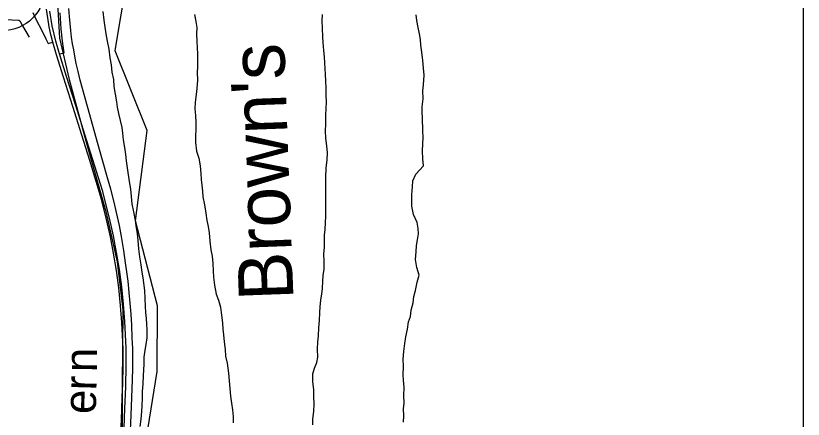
# Model space of a CAD drawing. Extents: x 2.1 to 8.9, y 14.1 to 20.9.
# Drawn here: x 7.533 to 8.9, y 15.741 to 16.441 of the extents above; entities that cross this region are included whole.
import ezdxf

# ---------------------------------------------------------------- set-up
doc = ezdxf.new("R2010")
doc.units = 0
for name, color, linetype in [('Default', 7, 'Continuous'), ('GM_X_City_Street', 7, 'Continuous'), ('GM_X_Major_River_Text', 7, 'Continuous'), ('GM_X_Rail_Line_Text', 7, 'Continuous'), ('GM_X_State_Location', 7, 'Continuous'), ('GM_X_State_Route', 7, 'Continuous'), ('GM_X_Unincorporated', 7, 'Continuous'), ('GM_X_Unincorporated_Location', 7, 'Continuous'), ('SC_Shading1', 7, 'Continuous'), ('SH_Cut_Line', 7, 'Continuous'), ('SH_Data', 7, 'Continuous')]:
    doc.layers.add(name, color=color, linetype=linetype)

msp = doc.modelspace()

# ---------------------------------------------------------------- linework, layer by layer
at = {"layer": 'Default'}
for p, q in [((7.7134, 16.4295), (7.7293, 16.5242)), ((7.7053, 16.3805), (7.7134, 16.4295)), ((7.7608, 16.2423), (7.7053, 16.3805)), ((7.7406, 16.0851), (7.7608, 16.2423)), ((7.7787, 15.9377), (7.7406, 16.0851)), ((7.7783, 15.8237), (7.7787, 15.9377)), ((7.7451, 15.6232), (7.7783, 15.8237))]:
    msp.add_line(p, q, dxfattribs=at)
at = {"layer": 'GM_X_City_Street'}
for p, q in [((7.4987, 16.4351), (7.5381, 16.4333)), ((7.5381, 16.4333), (7.5399, 16.4324)), ((7.5399, 16.4324), (7.5445, 16.4235)), ((7.5445, 16.4235), (7.5557, 16.4041))]:
    msp.add_line(p, q, dxfattribs=at)
at = {"layer": 'GM_X_Rail_Line_Text'}
for p, q in [((7.588, 16.4374), (7.5861, 16.4524)), ((7.5907, 16.4217), (7.588, 16.4374)), ((7.5958, 16.4236), (7.5916, 16.4493)), ((7.6019, 16.3969), (7.5958, 16.4236)), ((7.5937, 16.4084), (7.5907, 16.4217)), ((7.5968, 16.3954), (7.5937, 16.4084)), ((7.6084, 16.375), (7.6019, 16.3969)), ((7.6033, 16.3735), (7.5968, 16.3954)), ((7.6155, 16.3345), (7.6033, 16.3735)), ((7.6206, 16.336), (7.6084, 16.375)), ((7.6315, 16.2839), (7.6155, 16.3345)), ((7.6366, 16.2853), (7.6206, 16.336)), ((7.6473, 16.2339), (7.6315, 16.2839)), ((7.6524, 16.2354), (7.6366, 16.2853)), ((7.6612, 16.1898), (7.6473, 16.2339)), ((7.6663, 16.1913), (7.6524, 16.2354)), ((7.6795, 16.1487), (7.6663, 16.1913)), ((7.6723, 16.1538), (7.6612, 16.1898)), ((7.6807, 16.1249), (7.6723, 16.1538)), ((7.6835, 16.1363), (7.6795, 16.1487)), ((7.6901, 16.1104), (7.6835, 16.1363)), ((7.6854, 16.1068), (7.6807, 16.1249)), ((7.6954, 16.0899), (7.6901, 16.1104)), ((7.6903, 16.0879), (7.6854, 16.1068)), ((7.6971, 16.0576), (7.6903, 16.0879)), ((7.7022, 16.0591), (7.6954, 16.0899)), ((7.7024, 16.0291), (7.6971, 16.0576)), ((7.7074, 16.0306), (7.7022, 16.0591)), ((7.7072, 15.9989), (7.7024, 16.0291)), ((7.7124, 16.0008), (7.7074, 16.0306)), ((7.7165, 15.9707), (7.7124, 16.0008)), ((7.7114, 15.9688), (7.7072, 15.9989)), ((7.7146, 15.9386), (7.7114, 15.9688)), ((7.7197, 15.9407), (7.7165, 15.9707)), ((7.7168, 15.9087), (7.7146, 15.9386)), ((7.7222, 15.9106), (7.7197, 15.9407)), ((7.7181, 15.8861), (7.7168, 15.9087)), ((7.7233, 15.888), (7.7222, 15.9106)), ((7.7188, 15.8632), (7.7181, 15.8861)), ((7.7241, 15.8641), (7.7233, 15.888)), ((7.719, 15.833), (7.7188, 15.8632)), ((7.7244, 15.8351), (7.7241, 15.8641)), ((7.7184, 15.8024), (7.719, 15.833)), ((7.7235, 15.7971), (7.7244, 15.8351)), ((7.7176, 15.7797), (7.7184, 15.8024)), ((7.7222, 15.7595), (7.7235, 15.7971)), ((7.7167, 15.7573), (7.7176, 15.7797)), ((7.7157, 15.7267), (7.7167, 15.7573)), ((7.7202, 15.7063), (7.7222, 15.7595))]:
    msp.add_line(p, q, dxfattribs=at)
at = {"layer": 'GM_X_State_Location'}
for p, q in [((7.6836, 16.4485), (7.6854, 16.4334)), ((7.8432, 16.4432), (7.8453, 16.4315)), ((8.0647, 16.4322), (8.0649, 16.4432)), ((8.2292, 16.4331), (8.2279, 16.4429)), ((7.6854, 16.4334), (7.6875, 16.4212)), ((7.8453, 16.4315), (7.8467, 16.4209)), ((8.0653, 16.4197), (8.0647, 16.4322)), ((8.2313, 16.4206), (8.2292, 16.4331)), ((7.6875, 16.4212), (7.6892, 16.4099)), ((7.6892, 16.4099), (7.6914, 16.397)), ((7.8467, 16.4209), (7.8465, 16.4098)), ((7.8465, 16.4098), (7.8471, 16.3966)), ((8.066, 16.4049), (8.0653, 16.4197)), ((8.2334, 16.41), (8.2313, 16.4206)), ((8.2351, 16.4002), (8.2334, 16.41)), ((7.6914, 16.397), (7.6939, 16.383)), ((7.8471, 16.3966), (7.8477, 16.3859)), ((8.0662, 16.395), (8.066, 16.4049)), ((8.236, 16.3903), (8.2351, 16.4002)), ((7.6939, 16.383), (7.6961, 16.3682)), ((7.8477, 16.3859), (7.8483, 16.3746)), ((8.0676, 16.381), (8.0662, 16.395)), ((8.2378, 16.3778), (8.236, 16.3903)), ((7.8483, 16.3746), (7.8481, 16.3632)), ((8.0686, 16.37), (8.0676, 16.381)), ((8.0695, 16.3598), (8.0686, 16.37)), ((8.2396, 16.3638), (8.2378, 16.3778)), ((7.6961, 16.3682), (7.6982, 16.3561)), ((7.6982, 16.3561), (7.6996, 16.3432)), ((7.8481, 16.3632), (7.848, 16.3525)), ((8.0701, 16.3492), (8.0695, 16.3598)), ((8.2406, 16.3505), (8.2396, 16.3638)), ((7.6996, 16.3432), (7.7021, 16.3308)), ((7.848, 16.3525), (7.8474, 16.3426)), ((7.8474, 16.3426), (7.848, 16.3294)), ((8.0706, 16.3397), (8.0701, 16.3492)), ((8.2416, 16.3384), (8.2406, 16.3505)), ((7.7021, 16.3308), (7.7031, 16.3183)), ((7.848, 16.3294), (7.8471, 16.3149)), ((8.0712, 16.3279), (8.0706, 16.3397)), ((8.0718, 16.3162), (8.0712, 16.3279)), ((8.2404, 16.3213), (8.2416, 16.3384)), ((7.7031, 16.3183), (7.7052, 16.305)), ((7.8471, 16.3149), (7.8458, 16.3046)), ((8.0717, 16.3036), (8.0718, 16.3162)), ((8.2394, 16.311), (8.2404, 16.3213)), ((7.7052, 16.305), (7.7074, 16.2921)), ((7.8458, 16.3046), (7.8438, 16.2913)), ((8.0719, 16.2911), (8.0717, 16.3036)), ((8.2401, 16.2973), (8.2394, 16.311)), ((7.7074, 16.2921), (7.7087, 16.2823)), ((7.8438, 16.2913), (7.8436, 16.2799)), ((8.0717, 16.2808), (8.0719, 16.2911)), ((8.2384, 16.2833), (8.2401, 16.2973)), ((7.7087, 16.2823), (7.7112, 16.2717)), ((7.8436, 16.2799), (7.8446, 16.2682)), ((8.0712, 16.2679), (8.0717, 16.2808)), ((8.2382, 16.2738), (8.2384, 16.2833)), ((8.2388, 16.2643), (8.2382, 16.2738)), ((7.7112, 16.2717), (7.7137, 16.2596)), ((7.7137, 16.2596), (7.7165, 16.2475)), ((7.8446, 16.2682), (7.8452, 16.2557)), ((8.0708, 16.2531), (8.0712, 16.2679)), ((8.2392, 16.2415), (8.2388, 16.2643)), ((7.7165, 16.2475), (7.7179, 16.2373)), ((7.8452, 16.2557), (7.8455, 16.2435)), ((8.0706, 16.2417), (8.0708, 16.2531)), ((7.7179, 16.2373), (7.7192, 16.2259)), ((7.8449, 16.2329), (7.8447, 16.2215)), ((7.8455, 16.2435), (7.8449, 16.2329)), ((8.0712, 16.2288), (8.0706, 16.2417)), ((8.2398, 16.2298), (8.2392, 16.2415)), ((7.7192, 16.2259), (7.7214, 16.2127)), ((7.8447, 16.2215), (7.8466, 16.2063)), ((8.073, 16.2156), (8.0712, 16.2288)), ((8.2391, 16.2066), (8.2397, 16.2187)), ((8.2397, 16.2187), (8.2398, 16.2298)), ((7.7214, 16.2127), (7.7231, 16.2002)), ((7.8466, 16.2063), (7.8506, 16.1939)), ((8.0736, 16.2031), (8.073, 16.2156)), ((8.2394, 16.1929), (8.2391, 16.2066)), ((7.7231, 16.2002), (7.7245, 16.1896)), ((7.8506, 16.1939), (7.8527, 16.1806)), ((8.0735, 16.1909), (8.0736, 16.2031)), ((8.2404, 16.1808), (8.2394, 16.1929)), ((7.7245, 16.1896), (7.7262, 16.1775)), ((7.7262, 16.1775), (7.7293, 16.1536)), ((7.8527, 16.1806), (7.8537, 16.1674)), ((8.0718, 16.1768), (8.0735, 16.1909)), ((8.2274, 16.1661), (8.2404, 16.1808)), ((7.8537, 16.1674), (7.8547, 16.1571)), ((8.071, 16.1612), (8.0718, 16.1768)), ((8.2223, 16.1546), (8.2274, 16.1661)), ((7.7293, 16.1536), (7.7315, 16.14)), ((7.8547, 16.1571), (7.8556, 16.1473)), ((8.0707, 16.1381), (8.0712, 16.151)), ((8.0712, 16.151), (8.071, 16.1612)), ((8.2217, 16.1444), (8.2223, 16.1546)), ((7.7315, 16.14), (7.7328, 16.1275)), ((7.8556, 16.1473), (7.857, 16.1367)), ((7.857, 16.1367), (7.8575, 16.1268)), ((8.0712, 16.1282), (8.0707, 16.1381)), ((8.2205, 16.1307), (8.2217, 16.1444)), ((7.7328, 16.1275), (7.7342, 16.1146)), ((7.8575, 16.1268), (7.8601, 16.1132)), ((8.0708, 16.1126), (8.0712, 16.1282)), ((8.2203, 16.1212), (8.2205, 16.1307)), ((7.7342, 16.1146), (7.7368, 16.101)), ((7.8601, 16.1132), (7.8626, 16.0984)), ((8.071, 16.1028), (8.0708, 16.1126)), ((8.2205, 16.1109), (8.2203, 16.1212)), ((8.223, 16.0962), (8.2205, 16.1109)), ((7.7368, 16.101), (7.7397, 16.0862)), ((7.8626, 16.0984), (7.8644, 16.0859)), ((8.0708, 16.0929), (8.071, 16.1028)), ((8.2294, 16.0823), (8.223, 16.0962)), ((7.7397, 16.0862), (7.741, 16.0764)), ((7.8644, 16.0859), (7.8668, 16.0757)), ((8.0697, 16.0705), (8.0702, 16.0823)), ((8.0702, 16.0823), (8.0708, 16.0929)), ((8.2311, 16.072), (8.2294, 16.0823)), ((7.741, 16.0764), (7.7432, 16.0635)), ((7.8668, 16.0757), (7.8682, 16.0644)), ((8.0687, 16.0602), (8.0697, 16.0705)), ((8.2316, 16.0626), (8.2311, 16.072)), ((7.7432, 16.0635), (7.7445, 16.051)), ((7.8682, 16.0644), (7.8696, 16.05)), ((8.0686, 16.0496), (8.0687, 16.0602)), ((8.2299, 16.0523), (8.2316, 16.0626)), ((7.7445, 16.051), (7.7459, 16.037)), ((7.8696, 16.05), (7.8714, 16.0348)), ((8.0684, 16.0397), (8.0686, 16.0496)), ((8.2277, 16.0317), (8.2286, 16.0424)), ((8.2286, 16.0424), (8.2299, 16.0523)), ((7.7459, 16.037), (7.7477, 16.023)), ((7.8714, 16.0348), (7.8735, 16.0239)), ((8.0675, 16.0276), (8.0684, 16.0397)), ((8.0681, 16.0158), (8.0675, 16.0276)), ((8.2264, 16.0181), (8.2277, 16.0317)), ((7.7477, 16.023), (7.7499, 16.009)), ((7.8735, 16.0239), (7.8749, 16.0117)), ((8.068, 16.0014), (8.0681, 16.0158)), ((8.229, 16.0041), (8.2264, 16.0181)), ((7.7499, 16.009), (7.7516, 15.9961)), ((7.8749, 16.0117), (7.8751, 15.9977)), ((8.0663, 15.9903), (8.068, 16.0014)), ((8.233, 15.9912), (8.229, 16.0041)), ((7.7516, 15.9961), (7.7533, 15.9863)), ((7.7533, 15.9863), (7.756, 15.9643)), ((7.8751, 15.9977), (7.8757, 15.9878)), ((7.8757, 15.9878), (7.8775, 15.9738)), ((8.0657, 15.9805), (8.0663, 15.9903)), ((8.2298, 15.9787), (8.233, 15.9912)), ((7.8775, 15.9738), (7.8808, 15.9583)), ((8.0652, 15.9679), (8.0657, 15.9805)), ((8.2267, 15.9645), (8.2298, 15.9787)), ((7.756, 15.9643), (7.7567, 15.9507)), ((8.0642, 15.958), (8.0652, 15.9679)), ((8.2239, 15.9542), (8.2267, 15.9645)), ((7.7567, 15.9507), (7.7573, 15.9366)), ((7.8808, 15.9583), (7.8844, 15.9478)), ((7.8844, 15.9478), (7.8881, 15.9353)), ((8.0613, 15.936), (8.0625, 15.9485)), ((8.0625, 15.9485), (8.0642, 15.958)), ((8.2229, 15.9428), (8.2239, 15.9542)), ((7.7573, 15.9366), (7.7579, 15.9264)), ((7.8881, 15.9353), (7.8899, 15.9217)), ((8.0607, 15.9265), (8.0613, 15.936)), ((8.2194, 15.9303), (8.2229, 15.9428)), ((7.7579, 15.9264), (7.7589, 15.9158)), ((7.8899, 15.9217), (7.8916, 15.9085)), ((8.0598, 15.9124), (8.0607, 15.9265)), ((8.2148, 15.9101), (8.2181, 15.9196)), ((8.2181, 15.9196), (8.2194, 15.9303)), ((7.7589, 15.9158), (7.7598, 15.9059)), ((7.7598, 15.9059), (7.7604, 15.8965)), ((7.8916, 15.9085), (7.8922, 15.8975)), ((8.0589, 15.8999), (8.0598, 15.9124)), ((8.2128, 15.8975), (8.2148, 15.9101)), ((7.7604, 15.8965), (7.7599, 15.8824)), ((7.8922, 15.8975), (7.8932, 15.8876)), ((8.058, 15.8858), (8.0589, 15.8999)), ((8.21, 15.8842), (8.2128, 15.8975)), ((7.7599, 15.8824), (7.7582, 15.8706)), ((7.8932, 15.8876), (7.8945, 15.8751)), ((8.0571, 15.8755), (8.058, 15.8858)), ((8.2084, 15.8724), (8.21, 15.8842)), ((7.7582, 15.8706), (7.7565, 15.8611)), ((7.8945, 15.8751), (7.8959, 15.8622)), ((8.0566, 15.8626), (8.0571, 15.8755)), ((8.2067, 15.8587), (8.2084, 15.8724)), ((7.7565, 15.8611), (7.7552, 15.8489)), ((7.8959, 15.8622), (7.8969, 15.8505)), ((7.8969, 15.8505), (7.8994, 15.8384)), ((8.0572, 15.849), (8.0566, 15.8626)), ((8.2055, 15.8454), (8.2067, 15.8587)), ((7.7551, 15.8368), (7.7545, 15.8265)), ((7.7552, 15.8489), (7.7551, 15.8368)), ((7.8994, 15.8384), (7.902, 15.821)), ((8.0512, 15.8299), (8.0551, 15.8395)), ((8.0551, 15.8395), (8.0572, 15.849)), ((8.2057, 15.8328), (8.2055, 15.8454)), ((7.7545, 15.8265), (7.7539, 15.817)), ((8.0483, 15.82), (8.0512, 15.8299)), ((8.2052, 15.818), (8.2057, 15.8328)), ((7.7539, 15.817), (7.7531, 15.8026)), ((7.902, 15.821), (7.9034, 15.8074)), ((8.0482, 15.8059), (8.0483, 15.82)), ((8.2058, 15.8086), (8.2052, 15.818)), ((8.2072, 15.7961), (8.2058, 15.8086)), ((7.7531, 15.8026), (7.7522, 15.7889)), ((7.9034, 15.8074), (7.9041, 15.7941)), ((8.05, 15.7927), (8.0482, 15.8059)), ((8.2067, 15.7824), (8.2072, 15.7961)), ((7.7522, 15.7889), (7.752, 15.7768)), ((7.9041, 15.7941), (7.9054, 15.7812)), ((7.9054, 15.7812), (7.9072, 15.7691)), ((8.0502, 15.7805), (8.05, 15.7927)), ((8.2069, 15.7687), (8.2067, 15.7824)), ((7.752, 15.7768), (7.7515, 15.7642)), ((7.9072, 15.7691), (7.9089, 15.7574)), ((8.0508, 15.7673), (8.0502, 15.7805)), ((8.0503, 15.7547), (8.0508, 15.7673)), ((8.206, 15.7592), (8.2069, 15.7687)), ((7.7506, 15.7544), (7.7497, 15.7411)), ((7.7515, 15.7642), (7.7506, 15.7544)), ((7.9089, 15.7574), (7.9099, 15.7456)), ((8.0483, 15.7414), (8.0503, 15.7547)), ((8.2062, 15.7467), (8.206, 15.7592)), ((7.7497, 15.7411), (7.748, 15.7285)), ((7.9099, 15.7456), (7.9101, 15.7346)), ((8.0485, 15.7316), (8.0483, 15.7414)), ((8.206, 15.7361), (8.2062, 15.7467))]:
    msp.add_line(p, q, dxfattribs=at)
at = {"layer": 'GM_X_State_Route'}
msp.add_circle((7.509, 16.4895), 0.0744, dxfattribs=at)
at = {"layer": 'GM_X_Unincorporated'}
for p, q in [((7.5622, 16.4466), (7.5694, 16.4321)), ((7.6113, 16.4188), (7.6094, 16.4461)), ((7.5694, 16.4321), (7.5766, 16.4179)), ((7.5766, 16.4179), (7.5849, 16.4013)), ((7.6137, 16.3974), (7.6113, 16.4188)), ((7.5849, 16.4013), (7.5886, 16.393)), ((7.6165, 16.3766), (7.6137, 16.3974)), ((7.5886, 16.393), (7.5968, 16.3954)), ((7.6084, 16.375), (7.6165, 16.3766))]:
    msp.add_line(p, q, dxfattribs=at)
at = {"layer": 'SC_Shading1'}
for p, q in [((7.6037, 16.4827), (7.6085, 16.4025)), ((7.6257, 16.4399), (7.6247, 16.4537)), ((7.6268, 16.4276), (7.6257, 16.4399)), ((7.6282, 16.4155), (7.6268, 16.4276)), ((7.6295, 16.4038), (7.6282, 16.4155)), ((7.6085, 16.4025), (7.6255, 16.3308)), ((7.6313, 16.3924), (7.6295, 16.4038)), ((7.6331, 16.3821), (7.6313, 16.3924)), ((7.635, 16.3709), (7.6331, 16.3821)), ((7.6375, 16.3584), (7.635, 16.3709)), ((7.6407, 16.3443), (7.6375, 16.3584)), ((7.6444, 16.3295), (7.6407, 16.3443)), ((7.6255, 16.3308), (7.6559, 16.2179)), ((7.6572, 16.2836), (7.6444, 16.3295)), ((7.6757, 16.2172), (7.6572, 16.2836)), ((7.6559, 16.2179), (7.6892, 16.1016)), ((7.6919, 16.1598), (7.6757, 16.2172)), ((7.6976, 16.14), (7.6919, 16.1598)), ((7.7034, 16.118), (7.6976, 16.14)), ((7.7075, 16.1), (7.7034, 16.118)), ((7.6892, 16.1016), (7.7086, 16.0141)), ((7.7124, 16.0772), (7.7075, 16.1)), ((7.716, 16.0579), (7.7124, 16.0772)), ((7.7201, 16.0339), (7.716, 16.0579)), ((7.7233, 16.0126), (7.7201, 16.0339)), ((7.7086, 16.0141), (7.7186, 15.9308)), ((7.7255, 15.997), (7.7233, 16.0126)), ((7.7276, 15.9808), (7.7255, 15.997)), ((7.7297, 15.9607), (7.7276, 15.9808)), ((7.7314, 15.9427), (7.7297, 15.9607)), ((7.7327, 15.9231), (7.7314, 15.9427)), ((7.7186, 15.9308), (7.7171, 15.7998)), ((7.7341, 15.904), (7.7327, 15.9231)), ((7.7349, 15.8822), (7.7341, 15.904)), ((7.7356, 15.8637), (7.7349, 15.8822)), ((7.7357, 15.8478), (7.7356, 15.8637)), ((7.7356, 15.8296), (7.7357, 15.8478)), ((7.7352, 15.8097), (7.7356, 15.8296)), ((7.7329, 15.7483), (7.7352, 15.8097)), ((7.7171, 15.7998), (7.717, 15.6642)), ((7.7259, 15.5718), (7.7329, 15.7483))]:
    msp.add_line(p, q, dxfattribs=at)
at = {"layer": 'SH_Cut_Line'}
for p, q in [((7.7134, 16.4295), (7.7293, 16.5242)), ((7.7053, 16.3805), (7.7134, 16.4295)), ((7.7608, 16.2423), (7.7053, 16.3805)), ((7.7406, 16.0851), (7.7608, 16.2423)), ((7.7787, 15.9377), (7.7406, 16.0851)), ((7.7783, 15.8237), (7.7787, 15.9377)), ((7.7451, 15.6232), (7.7783, 15.8237))]:
    msp.add_line(p, q, dxfattribs=at)
at = {"layer": 'SH_Data'}
msp.add_line((8.9, 20.9), (8.9, 14.1), dxfattribs=at)
msp.add_line((8.9, 20.9), (8.9, 14.1), dxfattribs=at)

# ---------------------------------------------------------------- texts
at = {"layer": 'GM_X_Major_River_Text'}
for s, rotation, p in [('n', 89.4784, (7.6734, 15.8226)), ('r', 88.4528, (7.6725, 15.7906)), ('e', 88.0873, (7.6712, 15.7494))]:
    msp.add_text(s, height=0.0566, rotation=rotation, dxfattribs=at).set_placement(p)
at = {"layer": 'GM_X_Unincorporated_Location'}
msp.add_text("Brown's", height=0.09474, rotation=92.0968, dxfattribs=at).set_placement((8.0149, 15.9485))

doc.saveas('drawing.dxf')
